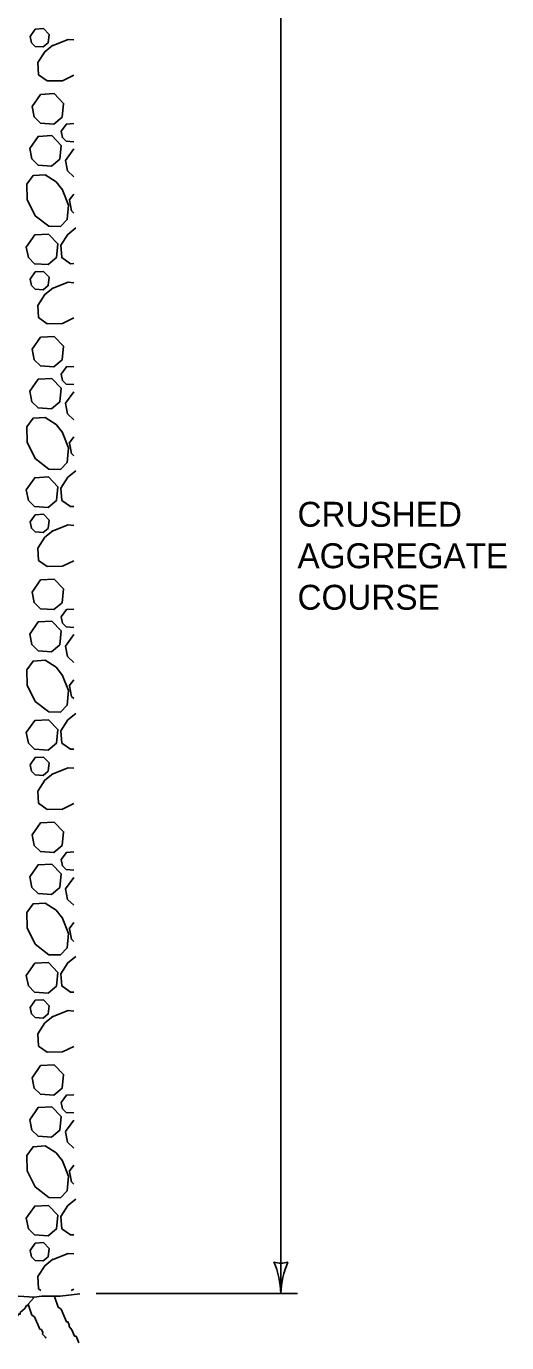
# Model space of a CAD drawing. Extents: x 49991.4 to 50021, y 49987.6 to 50011.4.
# Drawn here: x 50005.395 to 50006.554, y 49992.403 to 49995.576 of the extents above; entities that cross this region are included whole.
import ezdxf

# ---------------------------------------------------------------- set-up
doc = ezdxf.new("R2010")
doc.units = 0
for name, color, linetype in [('Level 1', 7, 'Continuous'), ('Level 2', 7, 'Continuous'), ('Level 3', 7, 'Continuous')]:
    doc.layers.add(name, color=color, linetype=linetype)

msp = doc.modelspace()

# ---------------------------------------------------------------- linework, layer by layer
at = {"layer": 'Level 1'}
for points in [[(50005.4042, 49995.5514), (50005.4165, 49995.5689), (50005.4362, 49995.57), (50005.4498, 49995.5559), (50005.4478, 49995.5361), (50005.4357, 49995.526), (50005.4163, 49995.5274), (50005.4072, 49995.5362), (50005.4043, 49995.5514)], [(50005.5092, 49995.4579), (50005.4824, 49995.4445), (50005.4454, 49995.4439), (50005.4246, 49995.4587), (50005.4226, 49995.4882), (50005.4395, 49995.5145), (50005.4589, 49995.53)], [(50005.4573, 49995.529), (50005.4957, 49995.5442), (50005.5092, 49995.543)], [(50005.4088, 49995.3825), (50005.4293, 49995.4116), (50005.462, 49995.4135), (50005.4847, 49995.3899), (50005.4814, 49995.3568), (50005.4612, 49995.34), (50005.4289, 49995.3424), (50005.4137, 49995.3571), (50005.4088, 49995.3825)], [(50005.4792, 49995.3227), (50005.4915, 49995.3402), (50005.5092, 49995.3412)], [(50005.4031, 49995.2812), (50005.4235, 49995.3104), (50005.4563, 49995.3123), (50005.479, 49995.2887), (50005.4757, 49995.2556), (50005.4555, 49995.2388), (50005.4232, 49995.2412), (50005.408, 49995.2559), (50005.4031, 49995.2812)], [(50005.5092, 49995.2974), (50005.4913, 49995.2987), (50005.4822, 49995.3075), (50005.4792, 49995.3227)], [(50005.4896, 49995.2523), (50005.5092, 49995.2801)], [(50005.5092, 49995.2128), (50005.4946, 49995.227), (50005.4896, 49995.2523)], [(50005.4813, 49995.1834), (50005.4965, 49995.145), (50005.4935, 49995.1098), (50005.4776, 49995.0931), (50005.449, 49995.0936), (50005.4165, 49995.119), (50005.3969, 49995.1583), (50005.3963, 49995.1953), (50005.4111, 49995.2161), (50005.4405, 49995.2181), (50005.4669, 49995.2012), (50005.4823, 49995.1818)], [(50005.4987, 49995.1564), (50005.5092, 49995.1712)], [(50005.5092, 49995.1257), (50005.5037, 49995.1311), (50005.4988, 49995.1564)], [(50005.3949, 49995.0437), (50005.4154, 49995.0728), (50005.4481, 49995.0747), (50005.4709, 49995.0511), (50005.4676, 49995.0181), (50005.4474, 49995.0013), (50005.415, 49995.0036), (50005.3999, 49995.0183), (50005.3949, 49995.0437)], [(50005.5092, 49995.0037), (50005.5012, 49995.0035), (50005.4803, 49995.0183), (50005.4784, 49995.0478), (50005.4953, 49995.0742), (50005.5146, 49995.0896)], [(50005.4042, 49994.9662), (50005.4165, 49994.9837), (50005.4362, 49994.9848), (50005.4498, 49994.9707), (50005.4478, 49994.9509), (50005.4357, 49994.9408), (50005.4163, 49994.9422), (50005.4072, 49994.951), (50005.4043, 49994.9662)], [(50005.4573, 49994.9438), (50005.4957, 49994.959), (50005.5092, 49994.9578)], [(50005.5092, 49994.8727), (50005.4824, 49994.8594), (50005.4454, 49994.8587), (50005.4246, 49994.8735), (50005.4226, 49994.903), (50005.4395, 49994.9293), (50005.4589, 49994.9448)], [(50005.4088, 49994.7973), (50005.4293, 49994.8264), (50005.462, 49994.8283), (50005.4847, 49994.8047), (50005.4814, 49994.7717), (50005.4612, 49994.7549), (50005.4289, 49994.7572), (50005.4137, 49994.7719), (50005.4088, 49994.7973)], [(50005.4792, 49994.7375), (50005.4915, 49994.755), (50005.5092, 49994.7561)], [(50005.4031, 49994.6961), (50005.4235, 49994.7252), (50005.4563, 49994.7271), (50005.479, 49994.7035), (50005.4757, 49994.6704), (50005.4555, 49994.6536), (50005.4232, 49994.656), (50005.408, 49994.6707), (50005.4031, 49994.696)], [(50005.5092, 49994.7122), (50005.4913, 49994.7135), (50005.4822, 49994.7223), (50005.4792, 49994.7375)], [(50005.4896, 49994.6671), (50005.5092, 49994.6949)], [(50005.5092, 49994.6276), (50005.4946, 49994.6418), (50005.4896, 49994.6671)], [(50005.4813, 49994.5982), (50005.4965, 49994.5599), (50005.4935, 49994.5246), (50005.4776, 49994.5079), (50005.449, 49994.5084), (50005.4165, 49994.5338), (50005.3969, 49994.5731), (50005.3963, 49994.6101), (50005.4111, 49994.6309), (50005.4405, 49994.6329), (50005.4669, 49994.616), (50005.4823, 49994.5966)], [(50005.4987, 49994.5712), (50005.5092, 49994.586)], [(50005.5092, 49994.5406), (50005.5037, 49994.5459), (50005.4988, 49994.5712)], [(50005.5092, 49994.4185), (50005.5012, 49994.4184), (50005.4803, 49994.4332), (50005.4784, 49994.4626), (50005.4953, 49994.489), (50005.5146, 49994.5044)], [(50005.3949, 49994.4585), (50005.4154, 49994.4876), (50005.4481, 49994.4895), (50005.4709, 49994.4659), (50005.4676, 49994.4329), (50005.4474, 49994.4161), (50005.415, 49994.4184), (50005.3999, 49994.4332), (50005.3949, 49994.4585)], [(50005.4042, 49994.381), (50005.4165, 49994.3985), (50005.4362, 49994.3997), (50005.4498, 49994.3855), (50005.4478, 49994.3657), (50005.4357, 49994.3556), (50005.4163, 49994.357), (50005.4072, 49994.3659), (50005.4043, 49994.381)], [(50005.5092, 49994.2875), (50005.4824, 49994.2742), (50005.4454, 49994.2735), (50005.4246, 49994.2883), (50005.4226, 49994.3178), (50005.4395, 49994.3441), (50005.4589, 49994.3596)], [(50005.4573, 49994.3586), (50005.4957, 49994.3738), (50005.5092, 49994.3726)], [(50005.4088, 49994.2121), (50005.4293, 49994.2412), (50005.462, 49994.2431), (50005.4847, 49994.2195), (50005.4814, 49994.1865), (50005.4612, 49994.1697), (50005.4289, 49994.172), (50005.4137, 49994.1868), (50005.4088, 49994.2121)], [(50005.4792, 49994.1524), (50005.4915, 49994.1698), (50005.5092, 49994.1709)], [(50005.4031, 49994.1109), (50005.4235, 49994.14), (50005.4563, 49994.1419), (50005.479, 49994.1183), (50005.4757, 49994.0853), (50005.4555, 49994.0684), (50005.4232, 49994.0708), (50005.408, 49994.0855), (50005.4031, 49994.1109)], [(50005.5092, 49994.127), (50005.4913, 49994.1283), (50005.4822, 49994.1372), (50005.4792, 49994.1524)], [(50005.4896, 49994.0819), (50005.5092, 49994.1097)], [(50005.5092, 49994.0424), (50005.4946, 49994.0566), (50005.4896, 49994.0819)], [(50005.4813, 49994.013), (50005.4965, 49993.9747), (50005.4935, 49993.9395), (50005.4776, 49993.9227), (50005.449, 49993.9233), (50005.4165, 49993.9487), (50005.3969, 49993.9879), (50005.3963, 49994.0249), (50005.4111, 49994.0457), (50005.4405, 49994.0477), (50005.4669, 49994.0308), (50005.4823, 49994.0114)], [(50005.4987, 49993.986), (50005.5092, 49994.0009)], [(50005.5092, 49993.9554), (50005.5037, 49993.9607), (50005.4988, 49993.986)], [(50005.3949, 49993.8733), (50005.4154, 49993.9025), (50005.4481, 49993.9043), (50005.4709, 49993.8807), (50005.4676, 49993.8477), (50005.4474, 49993.8309), (50005.415, 49993.8332), (50005.3999, 49993.848), (50005.3949, 49993.8733)], [(50005.5092, 49993.8333), (50005.5012, 49993.8332), (50005.4803, 49993.848), (50005.4784, 49993.8774), (50005.4953, 49993.9038), (50005.5146, 49993.9192)], [(50005.4042, 49993.7959), (50005.4165, 49993.8134), (50005.4362, 49993.8145), (50005.4498, 49993.8003), (50005.4478, 49993.7805), (50005.4357, 49993.7704), (50005.4163, 49993.7718), (50005.4072, 49993.7807), (50005.4043, 49993.7959)], [(50005.5092, 49993.7024), (50005.4824, 49993.689), (50005.4454, 49993.6883), (50005.4246, 49993.7031), (50005.4226, 49993.7326), (50005.4395, 49993.759), (50005.4589, 49993.7744)], [(50005.4573, 49993.7734), (50005.4957, 49993.7886), (50005.5092, 49993.7874)], [(50005.4088, 49993.6269), (50005.4293, 49993.656), (50005.462, 49993.6579), (50005.4847, 49993.6343), (50005.4814, 49993.6013), (50005.4612, 49993.5845), (50005.4289, 49993.5868), (50005.4137, 49993.6016), (50005.4088, 49993.6269)], [(50005.4792, 49993.5672), (50005.4915, 49993.5847), (50005.5092, 49993.5857)], [(50005.4031, 49993.5257), (50005.4235, 49993.5548), (50005.4563, 49993.5567), (50005.479, 49993.5331), (50005.4757, 49993.5001), (50005.4555, 49993.4833), (50005.4232, 49993.4856), (50005.408, 49993.5003), (50005.4031, 49993.5257)], [(50005.5092, 49993.5418), (50005.4913, 49993.5431), (50005.4822, 49993.552), (50005.4792, 49993.5672)], [(50005.4896, 49993.4967), (50005.5092, 49993.5245)], [(50005.5092, 49993.4572), (50005.4946, 49993.4714), (50005.4896, 49993.4967)], [(50005.4813, 49993.4278), (50005.4965, 49993.3895), (50005.4935, 49993.3543), (50005.4776, 49993.3375), (50005.449, 49993.3381), (50005.4165, 49993.3635), (50005.3969, 49993.4027), (50005.3963, 49993.4397), (50005.4111, 49993.4605), (50005.4405, 49993.4625), (50005.4669, 49993.4456), (50005.4823, 49993.4263)], [(50005.4987, 49993.4008), (50005.5092, 49993.4157)], [(50005.5092, 49993.3702), (50005.5037, 49993.3755), (50005.4988, 49993.4008)], [(50005.5092, 49993.2481), (50005.5012, 49993.248), (50005.4803, 49993.2628), (50005.4784, 49993.2923), (50005.4953, 49993.3186), (50005.5146, 49993.334)], [(50005.3949, 49993.2881), (50005.4154, 49993.3173), (50005.4481, 49993.3191), (50005.4709, 49993.2956), (50005.4676, 49993.2625), (50005.4474, 49993.2457), (50005.415, 49993.248), (50005.3999, 49993.2628), (50005.3949, 49993.2881)], [(50005.4042, 49993.2107), (50005.4165, 49993.2282), (50005.4362, 49993.2293), (50005.4498, 49993.2151), (50005.4478, 49993.1953), (50005.4357, 49993.1852), (50005.4163, 49993.1866), (50005.4072, 49993.1955), (50005.4043, 49993.2107)], [(50005.4573, 49993.1882), (50005.4957, 49993.2034), (50005.5092, 49993.2023)], [(50005.5092, 49993.1172), (50005.4824, 49993.1038), (50005.4454, 49993.1032), (50005.4246, 49993.118), (50005.4226, 49993.1474), (50005.4395, 49993.1738), (50005.4589, 49993.1892)], [(50005.4088, 49993.0417), (50005.4293, 49993.0709), (50005.462, 49993.0727), (50005.4847, 49993.0491), (50005.4814, 49993.0161), (50005.4612, 49992.9993), (50005.4289, 49993.0016), (50005.4137, 49993.0164), (50005.4088, 49993.0417)], [(50005.4792, 49992.982), (50005.4915, 49992.9995), (50005.5092, 49993.0005)], [(50005.5092, 49992.9566), (50005.4913, 49992.9579), (50005.4822, 49992.9668), (50005.4792, 49992.982)], [(50005.4031, 49992.9405), (50005.4235, 49992.9696), (50005.4563, 49992.9715), (50005.479, 49992.9479), (50005.4757, 49992.9149), (50005.4555, 49992.8981), (50005.4232, 49992.9004), (50005.408, 49992.9152), (50005.4031, 49992.9405)], [(50005.4896, 49992.9116), (50005.5092, 49992.9393)], [(50005.5092, 49992.8721), (50005.4946, 49992.8862), (50005.4896, 49992.9115)], [(50005.4813, 49992.8426), (50005.4965, 49992.8043), (50005.4935, 49992.7691), (50005.4776, 49992.7523), (50005.449, 49992.7529), (50005.4165, 49992.7783), (50005.3969, 49992.8175), (50005.3963, 49992.8545), (50005.4111, 49992.8753), (50005.4405, 49992.8773), (50005.4669, 49992.8604), (50005.4823, 49992.8411)], [(50005.4987, 49992.8157), (50005.5092, 49992.8305)], [(50005.5092, 49992.785), (50005.5037, 49992.7903), (50005.4988, 49992.8157)], [(50005.3949, 49992.7029), (50005.4154, 49992.7321), (50005.4481, 49992.734), (50005.4709, 49992.7104), (50005.4676, 49992.6773), (50005.4474, 49992.6605), (50005.415, 49992.6629), (50005.3999, 49992.6776), (50005.3949, 49992.7029)], [(50005.5092, 49992.6629), (50005.5012, 49992.6628), (50005.4803, 49992.6776), (50005.4784, 49992.7071), (50005.4953, 49992.7334), (50005.5146, 49992.7489)], [(50005.4042, 49992.6255), (50005.4165, 49992.643), (50005.4362, 49992.6441), (50005.4498, 49992.63), (50005.4478, 49992.6101), (50005.4357, 49992.6), (50005.4163, 49992.6014), (50005.4072, 49992.6103), (50005.4043, 49992.6255)], [(50005.4299, 49992.529), (50005.4246, 49992.5328), (50005.4226, 49992.5622), (50005.4395, 49992.5886), (50005.4589, 49992.604)], [(50005.4573, 49992.603), (50005.4957, 49992.6182), (50005.5092, 49992.6171)], [(50004.5915, 49992.5182), (50004.7331, 49992.5121), (50004.7958, 49992.515), (50004.8738, 49992.5246), (50004.9473, 49992.5229), (50004.9694, 49992.5251), (50005.0135, 49992.5223), (50005.0655, 49992.5257), (50005.1056, 49992.5229), (50005.1243, 49992.5251), (50005.2085, 49992.5195), (50005.2668, 49992.5155), (50005.282, 49992.5178), (50005.3589, 49992.5127), (50005.377, 49992.515), (50005.4138, 49992.5127), (50005.4324, 49992.515), (50005.4765, 49992.5155), (50005.5237, 49992.5206)], [(50005.4087, 49992.5138), (50005.4121, 49992.5099), (50005.3996, 49992.4957), (50005.3996, 49992.4923), (50005.3957, 49992.4923), (50005.3917, 49992.4856), (50005.3798, 49992.4754), (50005.3798, 49992.4714), (50005.3759, 49992.472), (50005.3719, 49992.4646), (50005.3646, 49992.4618), (50005.36, 49992.4511), (50005.3521, 49992.4477), (50005.3521, 49992.4443), (50005.3442, 49992.4375), (50005.3437, 49992.4336), (50005.3403, 49992.4341), (50005.3363, 49992.4268), (50005.3323, 49992.4273), (50005.3323, 49992.4234), (50005.3244, 49992.4166), (50005.3239, 49992.4132), (50005.3205, 49992.4132), (50005.3165, 49992.4058)], [(50005.4629, 49992.5144), (50005.472, 49992.4884), (50005.4788, 49992.4839), (50005.4918, 49992.4533), (50005.4952, 49992.4533), (50005.4986, 49992.446), (50005.498, 49992.442), (50005.5048, 49992.4341), (50005.511, 49992.4189), (50005.515, 49992.4189), (50005.5217, 49992.403)], [(50005.5092, 49992.532), (50005.5031, 49992.529)], [(50005.3991, 49992.4957), (50005.4081, 49992.4697), (50005.4149, 49992.4652), (50005.4279, 49992.4352), (50005.4313, 49992.4347), (50005.4347, 49992.4273), (50005.4341, 49992.4234), (50005.4409, 49992.416), (50005.442, 49992.4138)]]:
    msp.add_lwpolyline(points, dxfattribs=at)
at = {"layer": 'Level 3'}
for p, q in [((50006.0092, 49995.9778), (50006.0092, 49992.5214)), ((50005.5637, 49992.5214), (50006.0492, 49992.5214))]:
    msp.add_line(p, q, dxfattribs=at)
for centre, radius, start, end in [((50006.0092, 49992.6496), 0.0548, 252.1388, 287.8612), ((50005.7765, 49992.5099), 0.233, 2.8273, 22.0772), ((50006.2313, 49992.5122), 0.2223, 157.456, 177.6395)]:
    msp.add_arc(centre, radius, start, end, dxfattribs=at)

# ---------------------------------------------------------------- texts
at = {"layer": 'Level 2'}
for s, p in [('CRUSHED', (50006.0492, 49994.3696)), ('AGGREGATE', (50006.0492, 49994.2696)), ('COURSE', (50006.0492, 49994.1696))]:
    msp.add_text(s, height=0.06, dxfattribs=at).set_placement(p)

doc.saveas('drawing.dxf')
